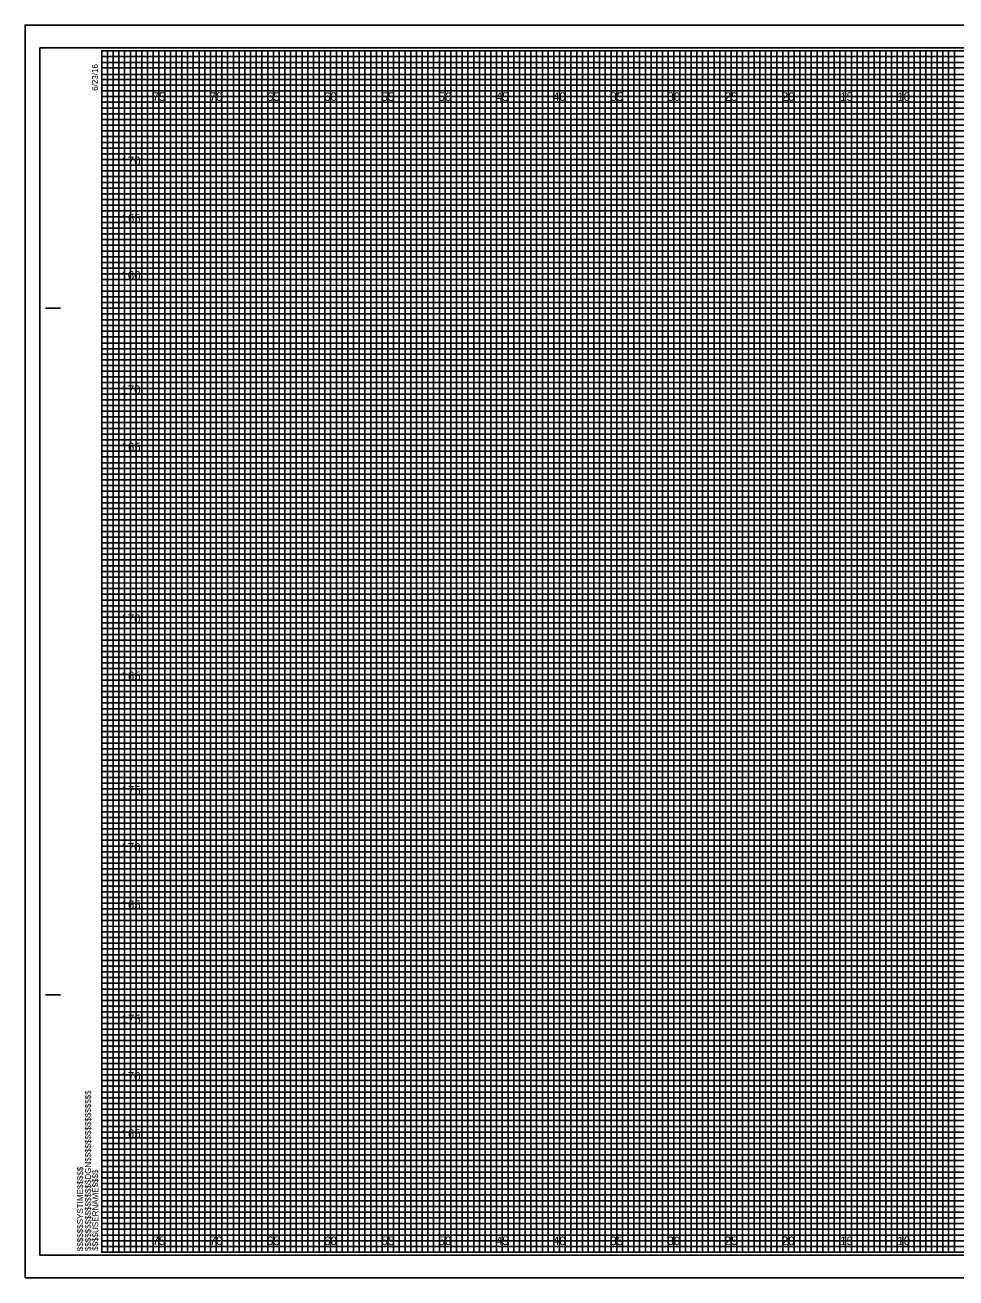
# Model space of a CAD drawing. Extents: x -7 to 162, y 1538 to 1647.
# Drawn here: x -6.7 to 74.6, y 1537.8 to 1647.2 of the extents above; entities that cross this region are included whole.
import ezdxf

# ---------------------------------------------------------------- set-up
doc = ezdxf.new("R2010")
doc.units = 0
for name, color, linetype in [('Prop CMT Pvmt Surface Shoulder', 7, 'Continuous'), ('Prop CMT Shld Paved Course 1', 7, 'Continuous'), ('Prop CMT Shld Paved Course 2', 7, 'Continuous'), ('Prop CMT Shld Paved Course 3', 7, 'Continuous'), ('Prop XS Ditch Standard Text', 7, 'Continuous'), ('Prop XS Elevation Labels', 7, 'Continuous'), ('Prop XS Finish Grade CurbGutter', 7, 'Continuous'), ('Sheet Cutting Line CELL', 7, 'Continuous'), ('Sheet DOT Grid CELL', 7, 'Continuous'), ('Sheet Plot Border Inside CELL', 7, 'Continuous'), ('Sheet Plot Border Outside CELL', 7, 'Continuous')]:
    doc.layers.add(name, color=color, linetype=linetype)

msp = doc.modelspace()

# ---------------------------------------------------------------- linework, layer by layer
at = {"layer": 'Prop CMT Pvmt Surface Shoulder'}
for p, q in [((0, 1644.5), (130, 1644.5)), ((130, 1643.99), (0, 1643.99)), ((0, 1643.99), (0, 1643.5)), ((0, 1643.5), (130, 1643.5)), ((130, 1642.94), (0, 1642.94)), ((0, 1642.94), (0, 1642)), ((0, 1642), (160, 1642))]:
    msp.add_line(p, q, dxfattribs=at)
for points in [[(0, 1641.5), (135, 1641.5), (160, 1641.5), (160, 1641), (0, 1641)], [(0, 1640.5), (160, 1640.5), (160, 1639.5), (0, 1639.5)], [(0, 1639), (160, 1639), (160, 1638.5), (0, 1638.49)], [(0, 1638), (160, 1638), (160, 1637), (0, 1637)], [(0, 1636.5), (160, 1636.5), (160, 1636), (0, 1636)], [(0, 1635.5), (160, 1635.5), (160, 1634.5), (0, 1634.5)], [(0, 1634), (160, 1634), (160, 1633.5), (0, 1633.5)], [(0, 1633), (160, 1633), (160, 1632), (0, 1632)], [(0, 1631.5), (160, 1631.5), (160, 1631), (0, 1631)], [(0, 1630.5), (160, 1630.5), (160, 1629.5), (0, 1629.5)], [(0, 1629), (160, 1629), (160, 1628.5), (0, 1628.5)], [(0, 1628), (160, 1628), (160, 1626.98), (160, 1626.5), (160, 1626), (0, 1626)], [(0, 1627), (160, 1627), (160, 1626.5), (0, 1626.5)], [(0, 1625.5), (160, 1625.5), (160, 1624.5), (0, 1624.52)], [(0, 1624.52), (160, 1624.5), (160, 1624), (0, 1624)], [(0, 1623.5), (160, 1623.5), (160, 1623), (0, 1623)], [(0, 1622), (160, 1622), (160, 1621.5), (0, 1621.5)], [(0, 1621), (160, 1621), (160, 1620.5), (0, 1620.5)], [(-0.04, 1619.44), (160, 1619.44), (160, 1618.94), (-0.04, 1618.94)], [(0, 1618.5), (160, 1618.5), (160, 1618), (0, 1618)], [(0, 1617), (160, 1617), (160, 1616.5), (0, 1616.5)], [(0, 1616), (160, 1616), (160, 1615.5), (0, 1615.5)], [(0, 1614.5), (160, 1614.5), (160, 1614), (0, 1614)], [(0, 1613.5), (160, 1613.5), (160, 1613), (0, 1613)], [(0, 1612), (160, 1612), (160, 1611.5), (0, 1611.5)], [(0, 1611), (160, 1611), (160, 1610.5), (0, 1610.5)], [(0, 1609.5), (160, 1609.5), (160, 1608.99), (0, 1609)], [(0, 1608.5), (160, 1608.5), (160, 1608), (0, 1608)], [(0, 1607), (160, 1607), (160, 1606.5), (0, 1606.5)], [(0, 1606), (160, 1606), (160, 1605.5), (0, 1605.5)], [(0, 1604.5), (160, 1604.5), (160, 1604), (0, 1604)], [(0, 1603.5), (160, 1603.5), (160, 1603), (0, 1603)], [(0, 1602), (160, 1602), (160, 1601.5), (0, 1601.5)], [(0, 1601), (160, 1601), (160, 1600.5), (0, 1600.5)], [(0, 1599.5), (160, 1599.5), (160, 1599), (0, 1599)], [(0, 1598.5), (160.03, 1598.45), (160, 1598), (0, 1598)], [(0, 1597), (160, 1597), (160, 1596.5), (0, 1596.5)], [(0, 1596), (160, 1596), (160, 1595.5), (0, 1595.5)], [(0, 1594.5), (160, 1594.5), (160, 1594), (0, 1594)], [(0, 1593.5), (160, 1593.5), (160, 1593), (0, 1593)], [(0, 1592), (160, 1592), (160, 1591.5), (0, 1591.5)], [(0, 1591), (160, 1591), (160, 1590.5), (0, 1590.5)], [(0, 1589.5), (160, 1589.5), (160, 1589), (0, 1589)], [(0, 1588.5), (160, 1588.5), (160, 1588), (0, 1588)], [(0, 1587), (160, 1587), (160, 1586.5), (0, 1586.5)], [(0, 1586), (160, 1586), (160, 1585.5), (0, 1585.5)], [(0, 1584.5), (160, 1584.5), (160, 1584), (0, 1584)], [(0, 1583.5), (160, 1583.5), (160, 1583), (0, 1583)], [(0, 1582), (160, 1582), (160, 1581.5), (0, 1581.5)], [(0, 1581), (160, 1581), (160, 1580.5), (0, 1580.5)], [(0, 1579.5), (160, 1579.5), (160, 1578.99), (0, 1579)], [(0, 1578.5), (160, 1578.5), (160, 1578), (0, 1578)], [(0, 1577), (160, 1577), (160, 1576.5), (0, 1576.5)], [(0, 1576), (160, 1576), (160, 1575.5), (0, 1575.5)], [(0, 1574.5), (160, 1574.5), (160, 1574), (0, 1574)], [(0, 1573.5), (160, 1573.5), (160, 1573), (0, 1573)], [(0, 1572), (160, 1572), (160, 1571.5), (0, 1571.5)], [(0, 1571), (160, 1571), (160, 1570.5), (0, 1570.5)], [(0, 1569.5), (160, 1569.5), (160, 1569), (0, 1569)], [(0, 1568.5), (160.03, 1568.45), (160, 1568), (0, 1568)], [(0, 1567), (160, 1567), (160, 1566.5), (0, 1566.5)], [(0, 1566), (160, 1566), (160, 1565.5), (0, 1565.5)], [(0, 1564.5), (160, 1564.5), (160, 1564), (0, 1564)], [(0, 1563.5), (160, 1563.5), (160, 1563), (0, 1563)], [(0, 1562), (160, 1562), (160, 1561.5), (0, 1561.5)], [(0, 1561), (160, 1561), (160, 1560.5), (0, 1560.5)], [(0, 1559.5), (160, 1559.5), (160, 1559), (0, 1559)], [(0, 1558.5), (160, 1558.5), (160, 1558), (0, 1558)], [(0, 1557), (160, 1557), (160, 1556.5), (0, 1556.5)], [(0, 1556), (160, 1556), (160, 1555.5), (0, 1555.5)], [(0, 1554.5), (160, 1554.5), (160, 1554), (0, 1554)], [(0, 1553.5), (160, 1553.5), (160, 1553), (0, 1553)], [(0, 1552), (160, 1552), (160, 1551.5), (0, 1551.5)], [(0, 1551), (160, 1551), (160, 1550.5), (0, 1550.5)], [(0, 1549.5), (160, 1549.5), (160, 1549), (0, 1549)], [(0, 1548.5), (160, 1548.5), (160, 1548), (0, 1548)], [(0, 1547), (160, 1547), (160, 1546.5), (0, 1546.5)], [(0, 1546), (160, 1546), (160, 1545.5), (0, 1545.5)], [(0, 1544.5), (160, 1544.5), (160, 1544), (0, 1544)], [(0, 1543.5), (160, 1543.5), (160, 1543), (0, 1543)], [(0, 1542), (160, 1542), (160, 1541.5), (0, 1541.5)], [(0, 1541), (160, 1541), (160, 1540.5), (0, 1540.5)]]:
    msp.add_lwpolyline(points, dxfattribs=at)
at = {"layer": 'Prop CMT Shld Paved Course 2'}
for p, q in [((5, 1645), (0, 1645)), ((5, 1540), (5, 1645)), ((15, 1645), (10, 1645)), ((10, 1645), (10, 1540)), ((15, 1540), (15, 1645)), ((25, 1645), (20, 1645)), ((20, 1645), (20, 1540)), ((25, 1540), (25, 1645)), ((35, 1645), (30, 1645)), ((30, 1645), (30, 1540)), ((35, 1540), (35, 1645)), ((45, 1645), (40, 1645)), ((40, 1645), (40, 1540)), ((45, 1540), (45, 1645)), ((55, 1645), (50, 1645)), ((50, 1645), (50, 1540)), ((55, 1540), (55, 1645)), ((65, 1645), (60, 1645)), ((60, 1645), (60, 1540)), ((65, 1540), (65, 1645)), ((75, 1645), (70, 1645)), ((70, 1645), (70, 1540)), ((10, 1540), (5, 1540)), ((20, 1540), (15, 1540)), ((30, 1540), (25, 1540)), ((40, 1540), (35, 1540)), ((50, 1540), (45, 1540)), ((60, 1540), (55, 1540)), ((70, 1540), (65, 1540))]:
    msp.add_line(p, q, dxfattribs=at)
for points in [[(0, 1640), (160, 1640), (160, 1635), (0, 1635)], [(0, 1630), (160, 1630), (160, 1625), (0, 1625)], [(0, 1620), (160, 1620), (160, 1615), (0, 1615)], [(0, 1610), (160, 1610), (160, 1605), (0, 1605)], [(0, 1600), (160, 1600), (160, 1595), (0, 1595)], [(0, 1590), (160, 1590), (160, 1585), (0, 1585)], [(0, 1580), (160, 1580), (160, 1575), (0, 1575)], [(0, 1570), (160, 1570), (160, 1565), (0, 1565)], [(0, 1560), (160, 1560), (160, 1555), (0, 1555)], [(0, 1550), (160, 1550), (160, 1545), (0, 1545)]]:
    msp.add_lwpolyline(points, dxfattribs=at)
at = {"layer": 'Prop CMT Shld Paved Course 3'}
for points in [[(0, 1645), (2.5, 1645), (2.5, 1540), (7.5, 1540), (7.5, 1645), (12.5, 1645), (12.5, 1540), (17.5, 1540), (17.5, 1645), (22.5, 1645), (22.5, 1540), (27.5, 1540), (27.5, 1645), (32.5, 1645), (32.5, 1540), (37.5, 1540), (37.5, 1645), (42.5, 1645), (42.5, 1540), (47.5, 1540), (47.5, 1645), (52.5, 1645), (52.5, 1540), (57.5, 1540), (57.5, 1645), (62.5, 1645), (62.5, 1540), (67.5, 1540), (67.5, 1645), (72.5, 1645), (72.5, 1540), (77.5, 1540)], [(0, 1642.5), (137.5, 1642.5)], [(0, 1632.5), (160, 1632.5), (160, 1637.5), (0, 1637.5)], [(0, 1622.5), (160, 1622.5), (160, 1627.5), (0, 1627.5)], [(0, 1612.5), (160, 1612.5), (160, 1617.5), (0, 1617.5)], [(0, 1602.5), (160, 1602.5), (160, 1607.5), (0, 1607.5)], [(0, 1592.5), (160, 1592.5), (160, 1597.5), (0, 1597.5)], [(0, 1582.5), (160, 1582.5), (160, 1587.5), (0, 1587.5)], [(0, 1572.5), (160, 1572.5), (160, 1577.5), (0, 1577.5)], [(0, 1562.5), (160, 1562.5), (160, 1567.5), (0, 1567.5)], [(0, 1552.5), (160, 1552.5), (160, 1557.5), (0, 1557.5)], [(0, 1542.5), (160, 1542.5), (160, 1547.5), (0, 1547.5)]]:
    msp.add_lwpolyline(points, dxfattribs=at)
at = {"layer": 'Prop XS Ditch Standard Text'}
for p, q in [((-4.9, 1622.5), (-3.65, 1622.5)), ((-4.85, 1622.5), (-3.6, 1622.5)), ((-4.9, 1562.5), (-3.65, 1562.5)), ((-4.85, 1562.5), (-3.6, 1562.5)), ((0, 1540), (0, 1540)), ((0, 1540), (0, 1540)), ((0, 1540), (0, 1540)), ((0, 1540), (0, 1540)), ((0, 1540), (0, 1540)), ((0, 1540), (0, 1540)), ((0, 1540), (0, 1540))]:
    msp.add_line(p, q, dxfattribs=at)
msp.add_lwpolyline([(160, 1645), (0, 1645), (0, 1540), (160, 1540)], close=True, dxfattribs=at)
at = {"layer": 'Prop XS Finish Grade CurbGutter'}
for points in [[(0, 1540), (0.5, 1540), (0.5, 1645), (1, 1645), (1, 1540)], [(1, 1540), (1.5, 1540), (1.5, 1645), (2, 1645), (2, 1540)], [(2.5, 1540), (3, 1540), (3, 1645), (3.5, 1645), (3.5, 1540)], [(3.5, 1540), (4, 1540), (4, 1645), (4.5, 1645), (4.5, 1540)], [(5, 1540), (5.5, 1540), (5.5, 1645), (6, 1645), (6, 1540)], [(6, 1540), (6.5, 1540), (6.5, 1645), (7, 1645), (7, 1540)], [(7.5, 1540), (8, 1540), (8, 1645), (8.5, 1645), (8.5, 1540)], [(8.5, 1540), (9, 1540), (9, 1645), (9.5, 1645), (9.5, 1540)], [(10, 1540), (10.5, 1540), (10.5, 1645), (11, 1645), (11, 1540)], [(11, 1540), (11.5, 1540), (11.5, 1645), (12, 1645), (12, 1540)], [(12.5, 1540), (13, 1540), (13, 1645), (13.5, 1645), (13.5, 1540)], [(13.5, 1540), (14, 1540), (14, 1645), (14.5, 1645), (14.5, 1540)], [(15, 1540), (15.5, 1540), (15.5, 1645), (16, 1645), (16, 1540)], [(16, 1540), (16.5, 1540), (16.5, 1645), (17, 1645), (17, 1540)], [(17.5, 1540), (18, 1540), (18, 1645), (18.5, 1645), (18.5, 1540)], [(18.5, 1540), (19, 1540), (19, 1645), (19.5, 1645), (19.5, 1540)], [(20, 1540), (20.5, 1540), (20.5, 1645), (21, 1645), (21, 1540)], [(21, 1540), (21.5, 1540), (21.5, 1645), (22, 1645), (22, 1540)], [(22.5, 1540), (23, 1540), (23, 1645), (23.5, 1645), (23.5, 1540)], [(23.5, 1540), (24, 1540), (24, 1645), (24.5, 1645), (24.5, 1540)], [(25, 1540), (25.5, 1540), (25.5, 1645), (26, 1645), (26, 1540)], [(26, 1540), (26.5, 1540), (26.5, 1645), (27, 1645), (27, 1540)], [(27.5, 1540), (28, 1540), (28, 1645), (28.5, 1645), (28.5, 1540)], [(28.5, 1540), (29, 1540), (29, 1645), (29.5, 1645), (29.5, 1540)], [(30, 1540), (30.5, 1540), (30.5, 1645), (31, 1645), (31, 1540)], [(31, 1540), (31.5, 1540), (31.5, 1645), (32, 1645), (32, 1540)], [(32.5, 1540), (33, 1540), (33, 1645), (33.5, 1645), (33.5, 1540)], [(33.5, 1540), (34, 1540), (34, 1645), (34.5, 1645), (34.5, 1540)], [(35, 1540), (35.5, 1540), (35.5, 1645), (36, 1645), (36, 1540)], [(36, 1540), (36.5, 1540), (36.5, 1645), (37, 1645), (37, 1540)], [(37.5, 1540), (38, 1540), (38, 1645), (38.5, 1645), (38.5, 1540)], [(38.5, 1540), (39, 1540), (39, 1645), (39.5, 1645), (39.5, 1540)], [(40, 1540), (40.5, 1540), (40.5, 1645), (41, 1645), (41, 1540)], [(41, 1540), (41.5, 1540), (41.5, 1645), (42, 1645), (42, 1540)], [(42.5, 1540), (43, 1540), (43, 1645), (43.5, 1645), (43.5, 1540)], [(43.5, 1540), (44, 1540), (44, 1645), (44.5, 1645), (44.5, 1540)], [(45, 1540), (45.5, 1540), (45.5, 1645), (46, 1645), (46, 1540)], [(46, 1540), (46.5, 1540), (46.5, 1645), (47, 1645), (47, 1540)], [(47.5, 1540), (48, 1540), (48, 1645), (48.5, 1645), (48.5, 1540)], [(48.5, 1540), (49, 1540), (49, 1645), (49.5, 1645), (49.5, 1540)], [(50, 1540), (50.5, 1540), (50.5, 1645), (51, 1645), (51, 1540)], [(51, 1540), (51.5, 1540), (51.5, 1645), (52, 1645), (52, 1540)], [(52.5, 1540), (53, 1540), (53, 1645), (53.5, 1645), (53.5, 1540)], [(53.5, 1540), (54, 1540), (54, 1645), (54.5, 1645), (54.5, 1540)], [(55, 1540), (55.5, 1540), (55.5, 1645), (56, 1645), (56, 1540)], [(56, 1540), (56.5, 1540), (56.5, 1645), (57, 1645), (57, 1540)], [(57.5, 1540), (58, 1540), (58, 1645), (58.5, 1645), (58.5, 1540)], [(58.5, 1540), (59, 1540), (59, 1645), (59.5, 1645), (59.5, 1540)], [(60, 1540), (60.5, 1540), (60.5, 1645), (61, 1645), (61, 1540)], [(61, 1540), (61.5, 1540), (61.5, 1645), (62, 1645), (62, 1540)], [(62.5, 1540), (63, 1540), (63, 1645), (63.5, 1645), (63.5, 1540)], [(63.5, 1540), (64, 1540), (64, 1645), (64.5, 1645), (64.5, 1540)], [(65, 1540), (65.5, 1540), (65.5, 1645), (66, 1645), (66, 1540)], [(66, 1540), (66.5, 1540), (66.5, 1645), (67, 1645), (67, 1540)], [(67.5, 1540), (68, 1540), (68, 1645), (68.5, 1645), (68.5, 1540)], [(68.5, 1540), (69, 1540), (69, 1645), (69.5, 1645), (69.5, 1540)], [(70, 1540), (70.5, 1540), (70.5, 1645), (71, 1645), (71, 1540)], [(71, 1540), (71.5, 1540), (71.5, 1645), (72, 1645), (72, 1540)], [(72.5, 1540), (73, 1540), (73, 1645), (73.5, 1645), (73.5, 1540)], [(73.5, 1540), (74, 1540), (74, 1645), (74.5, 1645), (74.5, 1540)]]:
    msp.add_lwpolyline(points, dxfattribs=at)
at = {"layer": 'Sheet Cutting Line CELL'}
for p, q in [((161.65, 1647.25), (-6.7, 1647.25)), ((-6.7, 1647.25), (-6.7, 1537.75)), ((-6.7, 1537.75), (161.65, 1537.75))]:
    msp.add_line(p, q, dxfattribs=at)
at = {"layer": 'Sheet DOT Grid CELL'}
for p, q in [((5, 1540), (5, 1645)), ((10, 1540), (10, 1645)), ((15, 1540), (15, 1645)), ((20, 1540), (20, 1645)), ((25, 1540), (25, 1645)), ((30, 1540), (30, 1645)), ((35, 1540), (35, 1645)), ((40, 1540), (40, 1645)), ((45, 1540), (45, 1645)), ((50, 1540), (50, 1645)), ((55, 1540), (55, 1645)), ((60, 1540), (60, 1645)), ((65, 1540), (65, 1645)), ((70, 1540), (70, 1645)), ((0, 1640), (160, 1640)), ((0, 1635), (160, 1635)), ((0, 1630), (160, 1630)), ((0, 1625), (160, 1625)), ((0, 1620), (160, 1620)), ((0, 1615), (160, 1615)), ((0, 1610), (160, 1610)), ((0, 1605), (160, 1605)), ((0, 1600), (160, 1600)), ((0, 1595), (160, 1595)), ((0, 1590), (160, 1590)), ((0, 1585), (160, 1585)), ((0, 1580), (160, 1580)), ((0, 1575), (160, 1575)), ((0, 1570), (160, 1570)), ((0, 1565), (160, 1565)), ((0, 1560), (160, 1560)), ((0, 1555), (160, 1555)), ((0, 1550), (160, 1550)), ((0, 1545), (160, 1545))]:
    msp.add_line(p, q, dxfattribs=at)
at = {"layer": 'Sheet Plot Border Inside CELL'}
msp.add_lwpolyline([(-5.4, 1539.75), (161.2, 1539.75), (161.2, 1645.25), (-5.4, 1645.25)], close=True, dxfattribs=at)
at = {"layer": 'Sheet Plot Border Outside CELL'}
msp.add_lwpolyline([(-6.7, 1537.75), (161.65, 1537.75), (161.65, 1647.25), (-6.7, 1647.25)], close=True, dxfattribs=at)

# ---------------------------------------------------------------- texts
at = {"layer": 'Prop CMT Shld Paved Course 1'}
for s, p in [('75', (4.44, 1640.62)), ('70', (9.43, 1640.62)), ('65', (14.44, 1640.62)), ('60', (19.43, 1640.62)), ('55', (24.44, 1640.62)), ('50', (29.43, 1640.62)), ('45', (34.44, 1640.62)), ('40', (39.43, 1640.62)), ('35', (44.44, 1640.62)), ('30', (49.43, 1640.62)), ('25', (54.44, 1640.62)), ('20', (59.43, 1640.62)), ('15', (64.53, 1640.62)), ('10', (69.52, 1640.62)), ('75', (4.44, 1540.62)), ('70', (9.43, 1540.62)), ('65', (14.44, 1540.62)), ('60', (19.43, 1540.62)), ('55', (24.44, 1540.62)), ('50', (29.43, 1540.62)), ('45', (34.44, 1540.62)), ('40', (39.43, 1540.62)), ('35', (44.44, 1540.62)), ('30', (49.43, 1540.62)), ('25', (54.44, 1540.62)), ('20', (59.43, 1540.62)), ('15', (64.53, 1540.62)), ('10', (69.52, 1540.62))]:
    msp.add_text(s, height=0.75, dxfattribs=at).set_placement(p)
at = {"layer": 'Prop XS Ditch Standard Text'}
for s, p in [('6/23/16', (-0.33, 1641.5)), ('$$$$$$$$$$$$$$$$DGN$$$$$$$$$$$$$$$$', (-0.94, 1540.09)), ('$$$$$$SYSTIME$$$$$', (-1.63, 1540.09)), ('$$$$USERNAME$$$$', (-0.31, 1540.12))]:
    msp.add_text(s, height=0.525, rotation=90, dxfattribs=at).set_placement(p)
at = {"layer": 'Prop XS Elevation Labels'}
for s, p in [('170', (1.72, 1635)), ('165', (1.73, 1630)), ('160', (1.72, 1625)), ('170', (1.72, 1615)), ('165', (1.73, 1610)), ('170', (1.72, 1595)), ('165', (1.73, 1590)), ('175', (1.73, 1580)), ('170', (1.72, 1575)), ('165', (1.73, 1570)), ('175', (1.73, 1560)), ('170', (1.72, 1555)), ('165', (1.73, 1550))]:
    msp.add_text(s, height=0.75, dxfattribs=at).set_placement(p)

doc.saveas('drawing.dxf')
